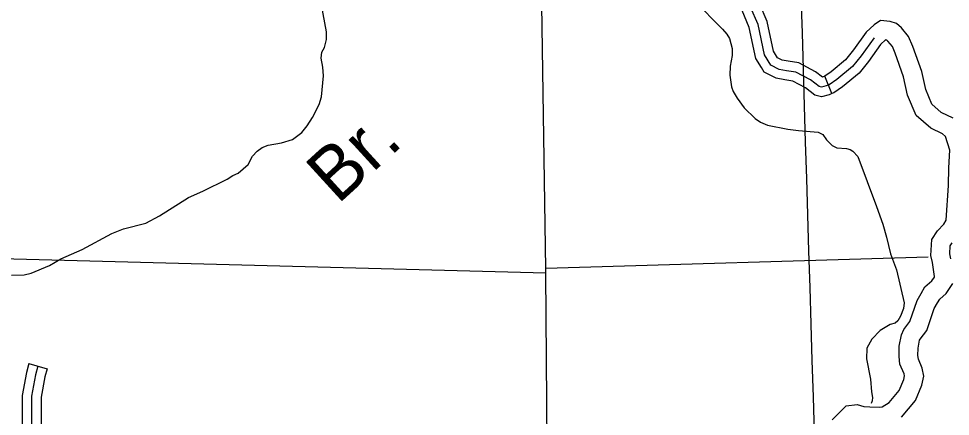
# Model space of a CAD drawing. Extents: x 1212896 to 1368412, y 378476 to 478763.
# Drawn here: x 1306302 to 1313715, y 394380 to 397540 of the extents above; entities that cross this region are included whole.
import ezdxf

# ---------------------------------------------------------------- set-up
doc = ezdxf.new("R2010")
doc.units = 0
for name, color, linetype in [('Level 35', 7, 'Continuous'), ('Level 4', 7, 'Continuous'), ('Level 45', 7, 'Continuous'), ('Level 46', 7, 'Continuous'), ('Level 5', 7, 'Continuous'), ('Level 60', 7, 'Continuous')]:
    doc.layers.add(name, color=color, linetype=linetype)

msp = doc.modelspace()

# ---------------------------------------------------------------- linework, layer by layer
at = {"layer": 'Level 35'}
for points in [[(1311675.7, 397685.9), (1311901.5, 397458.2), (1311936.7, 397417.2), (1311957.8, 397383.7), (1311978.4, 397304), (1311978.9, 397247), (1311964.5, 397163.4), (1311961.7, 397092.4), (1311974.5, 396999.3), (1311987.6, 396961.6), (1312020.3, 396907.5), (1312073.5, 396831.9), (1312161.9, 396748.3), (1312204.9, 396717.6), (1312260.6, 396695.3), (1312422.5, 396663), (1312505.8, 396650.5), (1312662.6, 396637.3), (1312700, 396618.9), (1312728.8, 396577.1), (1312775.2, 396531.4), (1312812.7, 396514.5), (1312887.8, 396508.7), (1312919, 396501.1), (1312939.4, 396488.2), (1312979.7, 396445.4), (1313128.7, 396047.9), (1313177, 395907.1), (1313207.1, 395804.7), (1313239.2, 395670.4), (1313285.5, 395543.3), (1313346.9, 395283.2), (1313341.9, 395236.6), (1313318.2, 395175.6), (1313298.3, 395139.9), (1313276, 395119.2), (1313235.3, 395109), (1313156.8, 395061.5), (1313091, 394993.4), (1313050.2, 394921), (1313046.8, 394836.7), (1313079.7, 394675.3), (1313086.8, 394574.3), (1313095.1, 394530.6), (1313093.9, 394504.3), (1313086.5, 394480.8)], [(1306244.5, 395500.7), (1306345.2, 395503.9), (1306400.7, 395517.1), (1306548.1, 395579.5), (1306638.7, 395631.6), (1306807.8, 395705.4), (1307044.5, 395831.9), (1307135.5, 395869), (1307313.1, 395915.9), (1307423.6, 395972.5), (1307652.9, 396118.8), (1307767.6, 396169.4), (1307962.1, 396264.9), (1308006.4, 396294.2), (1308047.8, 396312.9), (1308128.2, 396380.8), (1308163.6, 396448.7), (1308199.7, 396487.6), (1308240.9, 396517.6), (1308286.5, 396535), (1308394.8, 396553), (1308482, 396581), (1308555.6, 396636.7), (1308597.4, 396687.8), (1308640.8, 396755.9), (1308692.5, 396857.2), (1308712.1, 396918.8), (1308728.4, 397086.6), (1308722.9, 397154.6), (1308708.4, 397225.4), (1308715.2, 397273.2), (1308736.4, 397311.3), (1308752, 397375.7), (1308751.6, 397436.9), (1308712, 397650.5)]]:
    msp.add_lwpolyline(points, dxfattribs=at)
at = {"layer": 'Level 4'}
msp.add_lwpolyline([(1310516, 393126.8), (1310496.6, 395518.5), (1310496.7, 395554.6), (1310417.6, 400790.7), (1310418.6, 400868.9)], dxfattribs=at)
at = {"layer": 'Level 45'}
for p, q in [((1312773.5, 396944.8), (1312716.4, 397083.5)), ((1306384.1, 394798.9), (1306528.3, 394757.4))]:
    msp.add_line(p, q, dxfattribs=at)
for points in [[(1312410.8, 397126.5), (1312352.2, 397137.5), (1312287.1, 397170.3), (1312237.4, 397252.4), (1312185.2, 397493.8), (1312126.3, 397631.9), (1312070.1, 397783), (1312010.2, 397966.1), (1311951.5, 398093.2), (1311872.2, 398253.8), (1311698.1, 398455.5), (1311590.2, 398553.4), (1311519, 398749.3), (1311511.8, 398894.5), (1311520.2, 399014.9), (1311538.6, 399176.7), (1311595.4, 399453.6), (1311654.4, 399629.3), (1311693, 399734.4), (1311731, 399820.4), (1311859.4, 400063.8), (1311934.7, 400178.7), (1312054.4, 400288)], [(1312212.2, 397151.9), (1312168.1, 397224.8), (1312114.8, 397471.4), (1312057.9, 397604.6), (1312037.1, 397660.5)], [(1312340.5, 397229.5), (1312309.4, 397281), (1312258.3, 397517.1), (1312197.3, 397660.2), (1312177.7, 397712.8)], [(1313046.5, 397434.1), (1312946, 397292.1), (1312882, 397214.5), (1312766.4, 397118.3), (1312715.3, 397083)], [(1313108.2, 397389.1), (1313006.7, 397245.7), (1312936.4, 397160.4), (1312812.6, 397057.4), (1312751.9, 397015.5), (1312728.3, 397005.8), (1312689.6, 396995.6), (1312670.5, 397000), (1312601.9, 397054.1), (1312486.1, 397114.7), (1312410.8, 397126.5)], [(1313160, 397334.8), (1313065.2, 397201), (1312988.8, 397108.2), (1312857.2, 396998.7), (1312787.3, 396950.4), (1312773.5, 396944.8)], [(1312716.4, 397083.5), (1312703.9, 397078.3), (1312696.8, 397076.5), (1312643.6, 397118.4), (1312510.4, 397188.2), (1312423.8, 397201.8), (1312376.9, 397210.6), (1312341.1, 397228.6), (1312340.5, 397229.5)], [(1312773.5, 396944.8), (1312751.7, 396935.8), (1312690.7, 396919.7), (1312637.8, 396932), (1312561.7, 396992), (1312462.7, 397043.9), (1312398.3, 397053.9), (1312328.4, 397067.1), (1312235.1, 397114.1), (1312212.2, 397151.9)], [(1306384.1, 394798.9), (1306363.6, 394727.8), (1306330.6, 394546.5), (1306331, 394292), (1306333.5, 394251.7)], [(1306454.9, 394778.6), (1306435.4, 394711), (1306404.2, 394539.9), (1306404.6, 394294.3), (1306426.3, 393943), (1306420.8, 393694.3), (1306432.8, 393556.2), (1306440.4, 393389), (1306436.6, 393244.5), (1306410.7, 392964.4)], [(1306528.3, 394757.4), (1306509.9, 394693.5), (1306480.6, 394533.1), (1306481, 394296.7), (1306483.2, 394260.9)]]:
    msp.add_lwpolyline(points, dxfattribs=at)
at = {"layer": 'Level 46'}
for points in [[(1313738.6, 396750.7), (1313643.2, 396795.9), (1313567.9, 396860.9), (1313519.1, 396977.9), (1313488.1, 397120.3), (1313416.9, 397320.3), (1313383.6, 397399.2), (1313325.7, 397467.1), (1313286, 397501.5), (1313237.4, 397518.5), (1313160.4, 397525.4), (1313108.6, 397492), (1313046.5, 397434.1)], [(1312775.9, 394352.1), (1312885.7, 394464.7), (1312972.8, 394472.8), (1313026.7, 394457.7), (1313073.5, 394454.9), (1313152.6, 394452.8), (1313172.8, 394455.9), (1313229.4, 394488.6), (1313309.1, 394584.8), (1313345.3, 394671.6), (1313351.6, 394700.8), (1313348.1, 394717.6), (1313314.6, 394794.8), (1313307.3, 394855.5), (1313308.4, 394936.6), (1313326.9, 395028.6), (1313344.8, 395071), (1313394, 395134.5), (1313450.1, 395299.7), (1313483.3, 395357.2), (1313513.5, 395409.1), (1313568.7, 395456.2), (1313588.8, 395486.8), (1313589.2, 395492.2), (1313572.3, 395603.7), (1313558.9, 395658.7), (1313568.3, 395785.1), (1313613.5, 395854.8), (1313664.6, 395906.3), (1313682.4, 395939.3), (1313701.8, 396213.4), (1313702.4, 396354.1), (1313710.1, 396494.9), (1313675.8, 396602.7), (1313652, 396625.7), (1313560.6, 396669.1), (1313443.1, 396770.5), (1313375.4, 396932.7), (1313343.6, 397079.1), (1313277.1, 397265.9), (1313254.4, 397319.6), (1313219, 397361.1), (1313209.4, 397369.4), (1313205.4, 397370.8), (1313199.1, 397371.3), (1313160, 397334.8)], [(1313719.6, 395632.8), (1313710.2, 395671.3), (1313715, 395735.7), (1313730.9, 395760.1)], [(1313327.8, 394372.2), (1313438.9, 394506.3), (1313489.1, 394626.7), (1313504.9, 394700.2), (1313491.9, 394763.1), (1313460.9, 394834.4), (1313457.5, 394863.5), (1313458.2, 394920.8), (1313470.9, 394984.1), (1313475.3, 394994.5), (1313528, 395062.4), (1313587.4, 395237.5), (1313613.1, 395282), (1313630.3, 395311.6), (1313682.3, 395356), (1313734.8, 395435.9)]]:
    msp.add_lwpolyline(points, dxfattribs=at)
at = {"layer": 'Level 5'}
for points in [[(1310496.6, 395518.5), (1305051.5, 395660.5), (1299691.2, 395727.5), (1294412.5, 395761.3), (1292430.9, 395762.2)], [(1313539, 395644.1), (1310496.7, 395554.6)]]:
    msp.add_lwpolyline(points, dxfattribs=at)
at = {"layer": 'Level 60'}
msp.add_spline([(1312809.8, 388461.7), (1311685.6, 425480.9), (1311315.8, 437639.7)], degree=3, dxfattribs=at)

# ---------------------------------------------------------------- texts
at = {"layer": 'Level 35'}
msp.add_text('Br.', height=422.4, rotation=42.43152, dxfattribs=at).set_placement((1308840, 396058.3))

doc.saveas('drawing.dxf')
